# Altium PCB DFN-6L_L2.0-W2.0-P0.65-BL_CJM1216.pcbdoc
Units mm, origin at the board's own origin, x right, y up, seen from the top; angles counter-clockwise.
Board outline 14.9 x 15.59 mm, 2 copper layers (Top Layer, Bottom Layer), stack 0 mm thick; 1 components, 0 nets, 8 pads, 0 vias.
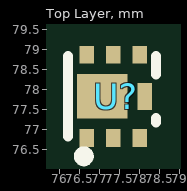
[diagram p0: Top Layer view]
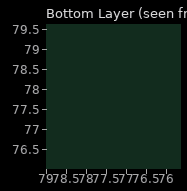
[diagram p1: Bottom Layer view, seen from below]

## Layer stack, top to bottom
Top Layer: signal copper (thickness not stored)
Bottom Layer: signal copper (thickness not stored)

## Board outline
84.75,69.85 69.85,69.85 69.85,85.437 84.75,85.437

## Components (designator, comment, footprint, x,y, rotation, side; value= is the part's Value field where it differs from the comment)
U? "" DFN-6L_L2.0-W2.0-P0.65-BL_CJM1216 77.4,77.824 r0 top

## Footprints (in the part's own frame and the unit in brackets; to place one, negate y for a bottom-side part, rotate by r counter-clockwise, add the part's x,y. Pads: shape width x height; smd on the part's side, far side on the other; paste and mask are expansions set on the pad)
DFN-6L_L2.0-W2.0-P0.65-BL_CJM1216 [mil]
  rect 14.5x17.5 smd: 1(-28.5,-40.94) 2(-2.5,-40.94) 3(23.5,-40.94) 4(23.5,40.94) 5(-2.5,40.94) 6(-28.5,40.94)
  rect 49.5x43.5 smd: 7(-13.5,0)
  rect 14.5x26.5 smd: 8(28.5,0)
  silkscreen extent -47,-64 39,39

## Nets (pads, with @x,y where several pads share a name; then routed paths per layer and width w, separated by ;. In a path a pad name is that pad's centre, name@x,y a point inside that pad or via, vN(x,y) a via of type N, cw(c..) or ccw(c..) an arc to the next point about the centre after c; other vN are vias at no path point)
pads on no net: U?.1 U?.2 U?.3 U?.4 U?.5 U?.6 U?.7 U?.8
